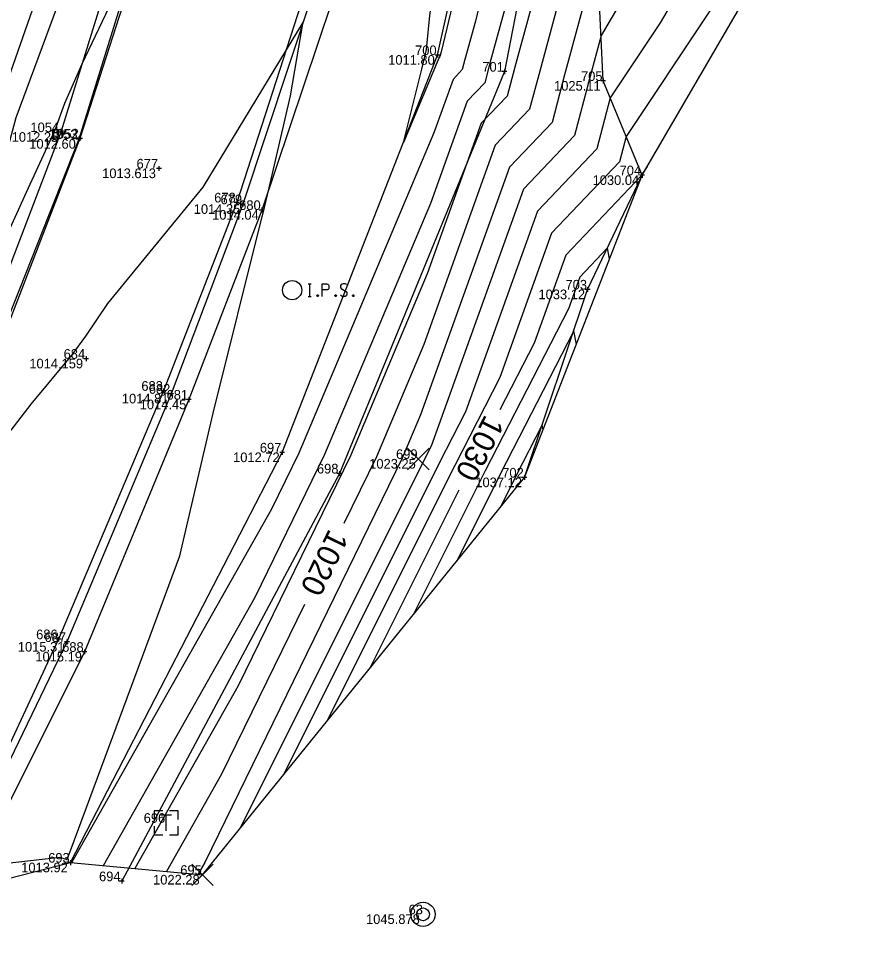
# Model space of a CAD drawing. Extents: x 2354693 to 2355622, y 637071 to 710080.
# Drawn here: x 2355324.5 to 2355430.4, y 708993.3 to 709108.7 of the extents above; entities that cross this region are included whole.
import ezdxf

# ---------------------------------------------------------------- set-up
doc = ezdxf.new("R2010")
doc.units = 0
for name, color, linetype in [('Default', 7, 'Continuous'), ('DT_X_Contour_Major', 7, 'Continuous'), ('DT_X_Contour_Minor', 7, 'Continuous'), ('PM_X_Surveyed_Line', 7, 'Continuous'), ('PV_X_EOP', 7, 'Continuous'), ('PV_X_Shoulder', 7, 'Continuous'), ('SV_P_Mon_Cells_Set', 7, 'Continuous'), ('SV_X_Mon_Cells_Found', 7, 'Continuous'), ('SV_X_Random_Point', 7, 'Continuous'), ('SV_X_Shot_Marker', 7, 'Continuous'), ('SV_X_Text_Elevation', 7, 'Continuous'), ('SV_X_Text_Name', 7, 'Continuous'), ('SV_X_Toe_of_Slope', 7, 'Continuous'), ('SV_X_Top_of_Bank', 7, 'Continuous'), ('UT_X_Telecom_Cells', 7, 'Continuous'), ('VG_X_Tree_Line_Rt', 7, 'Continuous')]:
    doc.layers.add(name, color=color, linetype=linetype)

msp = doc.modelspace()

# ---------------------------------------------------------------- linework, layer by layer
at = {"layer": 'Default'}
msp.add_lwpolyline([(2355263.76, 708986.4), (2355330.91, 709003.61), (2355347.35, 709002.09), (2355387.45, 709051.54), (2355402.1, 709089.16), (2355425.96, 709130.16), (2355495.56, 709194.41), (2355530.33, 709221.46), (2355525, 709302.12), (2355509.66, 709318.33), (2355534.8, 709413.26), (2355566.11, 709428.47), (2355585.74, 709473.78), (2355589.64, 709532.44), (2355608.23, 709591.27)], dxfattribs=at)
msp.add_lwpolyline([(2355263.76, 708986.4), (2355330.91, 709003.61), (2355347.35, 709002.09), (2355387.45, 709051.54), (2355402.1, 709089.16), (2355425.96, 709130.16), (2355495.56, 709194.41), (2355530.33, 709221.46), (2355525, 709302.12), (2355509.66, 709318.33), (2355534.8, 709413.26), (2355566.11, 709428.47), (2355585.74, 709473.78), (2355589.64, 709532.44), (2355608.23, 709591.27)], dxfattribs=at)
at = {"layer": 'DT_X_Contour_Major'}
for points in [[(2355347.04, 709193.49), (2355347.17, 709190.66), (2355346.28, 709182.54), (2355344.27, 709168.58), (2355339.69, 709145.3), (2355339.23, 709144.66), (2355328.8, 709128.82), (2355329.27, 709120.28), (2355328.85, 709117.46), (2355322.25, 709098.57)], [(2355347.04, 709193.49), (2355347.17, 709190.66), (2355346.28, 709182.54), (2355344.27, 709168.58), (2355339.69, 709145.3), (2355339.23, 709144.66), (2355328.8, 709128.82), (2355329.27, 709120.28), (2355328.85, 709117.46), (2355322.25, 709098.57)], [(2355399.81, 709138.75), (2355397.63, 709133.42), (2355395.27, 709124.59), (2355394.15, 709119.88), (2355389.34, 709102.14), (2355388.09, 709097.39), (2355383.82, 709092.9), (2355374.92, 709068.12), (2355369.01, 709054.1), (2355364.95, 709045.81)], [(2355399.81, 709138.75), (2355397.63, 709133.42), (2355395.27, 709124.59), (2355394.15, 709119.88), (2355389.34, 709102.14), (2355388.09, 709097.39), (2355383.82, 709092.9), (2355374.92, 709068.12), (2355369.01, 709054.1), (2355364.95, 709045.81)], [(2355402.74, 709090.26), (2355402.07, 709089.24), (2355402.06, 709089.19), (2355392.58, 709079.22), (2355388.65, 709068.27), (2355384.38, 709059.96)], [(2355402.74, 709090.26), (2355402.07, 709089.24), (2355402.06, 709089.19), (2355392.58, 709079.22), (2355388.65, 709068.27), (2355384.38, 709059.96)], [(2355379.29, 709049.98), (2355368.2, 709027.8)], [(2355379.29, 709049.98), (2355368.2, 709027.8)], [(2355360.04, 709035.75), (2355349.73, 709014.64), (2355342.86, 709002.51)], [(2355360.04, 709035.75), (2355349.73, 709014.64), (2355342.86, 709002.51)]]:
    msp.add_lwpolyline(points, dxfattribs=at)
at = {"layer": 'DT_X_Contour_Minor'}
for points in [[(2355432.86, 709227.06), (2355429.2, 709222.75), (2355423.82, 709215.5), (2355413.6, 709196.23), (2355417.38, 709191.51), (2355406.15, 709181.07), (2355401.67, 709175.4), (2355399.28, 709169.52), (2355396.31, 709163.17), (2355393.28, 709154.48), (2355391.12, 709148.5), (2355389.3, 709141.69), (2355381.34, 709108.35), (2355380.04, 709103.59), (2355379.71, 709102.31), (2355378.56, 709101.1), (2355376.17, 709094.45), (2355359.35, 709054.56), (2355355.96, 709047.61), (2355331.07, 709003.59)], [(2355432.86, 709227.06), (2355429.2, 709222.75), (2355423.82, 709215.5), (2355413.6, 709196.23), (2355417.38, 709191.51), (2355406.15, 709181.07), (2355401.67, 709175.4), (2355399.28, 709169.52), (2355396.31, 709163.17), (2355393.28, 709154.48), (2355391.12, 709148.5), (2355389.3, 709141.69), (2355381.34, 709108.35), (2355380.04, 709103.59), (2355379.71, 709102.31), (2355378.56, 709101.1), (2355376.17, 709094.45), (2355359.35, 709054.56), (2355355.96, 709047.61), (2355331.07, 709003.59)], [(2355433.91, 709212.05), (2355427.03, 709199.09), (2355429.57, 709195.91), (2355410.59, 709178.28), (2355405.76, 709172.16), (2355404.34, 709170.04), (2355400.84, 709164.36), (2355398.86, 709160.13), (2355398.29, 709158.51), (2355394.5, 709147.97), (2355391.29, 709135.99), (2355385.61, 709112.19), (2355383.14, 709103.1), (2355382.5, 709100.67), (2355380.31, 709098.37), (2355375.75, 709085.67), (2355362.57, 709054.41), (2355353.88, 709036.62), (2355335, 709003.23)], [(2355433.91, 709212.05), (2355427.03, 709199.09), (2355429.57, 709195.91), (2355410.59, 709178.28), (2355405.76, 709172.16), (2355404.34, 709170.04), (2355400.84, 709164.36), (2355398.86, 709160.13), (2355398.29, 709158.51), (2355394.5, 709147.97), (2355391.29, 709135.99), (2355385.61, 709112.19), (2355383.14, 709103.1), (2355382.5, 709100.67), (2355380.31, 709098.37), (2355375.75, 709085.67), (2355362.57, 709054.41), (2355353.88, 709036.62), (2355335, 709003.23)], [(2355455.82, 709201.52), (2355428.34, 709177.87), (2355423.54, 709166.09), (2355421.9, 709163.64), (2355420.2, 709160.88), (2355416.62, 709155.81), (2355407.85, 709141.74), (2355400.15, 709122.88), (2355396.5, 709116.66), (2355392.43, 709101.65), (2355390.88, 709095.75), (2355385.57, 709090.16), (2355374.5, 709059.34), (2355372.23, 709053.95), (2355347.65, 709003.65), (2355346.79, 709002.14)], [(2355455.82, 709201.52), (2355428.34, 709177.87), (2355423.54, 709166.09), (2355421.9, 709163.64), (2355420.2, 709160.88), (2355416.62, 709155.81), (2355407.85, 709141.74), (2355400.15, 709122.88), (2355396.5, 709116.66), (2355392.43, 709101.65), (2355390.88, 709095.75), (2355385.57, 709090.16), (2355374.5, 709059.34), (2355372.23, 709053.95), (2355347.65, 709003.65), (2355346.79, 709002.14)], [(2355401.7, 709183.87), (2355400.31, 709182.11), (2355394.55, 709167.89), (2355393.76, 709166.21), (2355388.26, 709150.46), (2355387.74, 709149.02), (2355387.31, 709147.39), (2355377.07, 709104.51), (2355376.95, 709104.07), (2355376.92, 709103.95), (2355376.81, 709103.84), (2355376.59, 709103.23), (2355372.38, 709093.25), (2355374.65, 709102.38), (2355375.23, 709104.82), (2355375.66, 709109.07), (2355380.92, 709145.65), (2355381.7, 709154.71), (2355384.94, 709165.98), (2355388.38, 709181.55), (2355387.25, 709201.61)], [(2355401.7, 709183.87), (2355400.31, 709182.11), (2355394.55, 709167.89), (2355393.76, 709166.21), (2355388.26, 709150.46), (2355387.74, 709149.02), (2355387.31, 709147.39), (2355377.07, 709104.51), (2355376.95, 709104.07), (2355376.92, 709103.95), (2355376.81, 709103.84), (2355376.59, 709103.23), (2355372.38, 709093.25), (2355374.65, 709102.38), (2355375.23, 709104.82), (2355375.66, 709109.07), (2355380.92, 709145.65), (2355381.7, 709154.71), (2355384.94, 709165.98), (2355388.38, 709181.55), (2355387.25, 709201.61)], [(2355441.77, 709200.32), (2355421.1, 709181.12), (2355415.48, 709176.27), (2355415, 709175.1), (2355410.19, 709167.9), (2355405.21, 709159.83), (2355399.33, 709151.49), (2355397.87, 709147.45), (2355393.28, 709130.29), (2355389.88, 709116.04), (2355386.24, 709102.62), (2355385.3, 709099.03), (2355382.07, 709095.63), (2355375.33, 709076.89), (2355365.79, 709054.26), (2355351.8, 709025.63), (2355338.93, 709002.87)], [(2355441.77, 709200.32), (2355421.1, 709181.12), (2355415.48, 709176.27), (2355415, 709175.1), (2355410.19, 709167.9), (2355405.21, 709159.83), (2355399.33, 709151.49), (2355397.87, 709147.45), (2355393.28, 709130.29), (2355389.88, 709116.04), (2355386.24, 709102.62), (2355385.3, 709099.03), (2355382.07, 709095.63), (2355375.33, 709076.89), (2355365.79, 709054.26), (2355351.8, 709025.63), (2355338.93, 709002.87)], [(2355362.05, 709192.16), (2355358.45, 709172.04), (2355357.11, 709166.59), (2355354.46, 709157.07), (2355350.37, 709143.12), (2355339.59, 709118.3), (2355339.54, 709118.17), (2355339.49, 709118.02), (2355332.34, 709102.98), (2355330.16, 709098.09), (2355328.96, 709094.77), (2355325.41, 709087), (2355319.12, 709073.27), (2355312.74, 709068.84), (2355306.43, 709059.31), (2355290.09, 709038.24), (2355286.78, 709031.66), (2355285.96, 709030.24), (2355285.39, 709028.91), (2355262.53, 708987.18)], [(2355362.05, 709192.16), (2355358.45, 709172.04), (2355357.11, 709166.59), (2355354.46, 709157.07), (2355350.37, 709143.12), (2355339.59, 709118.3), (2355339.54, 709118.17), (2355339.49, 709118.02), (2355332.34, 709102.98), (2355330.16, 709098.09), (2355328.96, 709094.77), (2355325.41, 709087), (2355319.12, 709073.27), (2355312.74, 709068.84), (2355306.43, 709059.31), (2355290.09, 709038.24), (2355286.78, 709031.66), (2355285.96, 709030.24), (2355285.39, 709028.91), (2355262.53, 708987.18)], [(2355434.77, 709178.67), (2355427.81, 709161.59), (2355427.75, 709161.5), (2355427.69, 709161.4), (2355427.56, 709161.22), (2355413.25, 709138.29), (2355407.86, 709125.05), (2355396.98, 709106.54), (2355395.53, 709101.17), (2355393.68, 709094.11), (2355387.32, 709087.42), (2355375.84, 709055.46), (2355374.95, 709053.73), (2355351.99, 709007.81)], [(2355434.77, 709178.67), (2355427.81, 709161.59), (2355427.75, 709161.5), (2355427.69, 709161.4), (2355427.56, 709161.22), (2355413.25, 709138.29), (2355407.86, 709125.05), (2355396.98, 709106.54), (2355395.53, 709101.17), (2355393.68, 709094.11), (2355387.32, 709087.42), (2355375.84, 709055.46), (2355374.95, 709053.73), (2355351.99, 709007.81)], [(2355443.81, 709170.88), (2355426.26, 709134.89), (2355424.07, 709131.37), (2355423.26, 709129.4), (2355420.36, 709124.46), (2355400.1, 709094.01), (2355399.26, 709090.83), (2355390.83, 709081.95), (2355384.38, 709064), (2355378.76, 709053.06), (2355362.8, 709021.14)], [(2355443.81, 709170.88), (2355426.26, 709134.89), (2355424.07, 709131.37), (2355423.26, 709129.4), (2355420.36, 709124.46), (2355400.1, 709094.01), (2355399.26, 709090.83), (2355390.83, 709081.95), (2355384.38, 709064), (2355378.76, 709053.06), (2355362.8, 709021.14)], [(2355435.74, 709166.06), (2355427.13, 709148.41), (2355418.66, 709134.83), (2355415.56, 709127.23), (2355404.35, 709108.14), (2355398.13, 709098.79), (2355396.47, 709092.47), (2355389.07, 709084.69), (2355380.11, 709059.73), (2355376.86, 709053.4), (2355357.39, 709014.47)], [(2355435.74, 709166.06), (2355427.13, 709148.41), (2355418.66, 709134.83), (2355415.56, 709127.23), (2355404.35, 709108.14), (2355398.13, 709098.79), (2355396.47, 709092.47), (2355389.07, 709084.69), (2355380.11, 709059.73), (2355376.86, 709053.4), (2355357.39, 709014.47)], [(2355355.09, 709085.15), (2355355.66, 709087.58), (2355358.32, 709099.04), (2355359.91, 709108.28), (2355347.41, 709087.68), (2355335.52, 709073.22), (2355332.79, 709069.12), (2355331.08, 709066.83), (2355325.98, 709060.69), (2355315.72, 709047.38)], [(2355355.09, 709085.15), (2355355.66, 709087.58), (2355358.32, 709099.04), (2355359.91, 709108.28), (2355347.41, 709087.68), (2355335.52, 709073.22), (2355332.79, 709069.12), (2355331.08, 709066.83), (2355325.98, 709060.69), (2355315.72, 709047.38)], [(2355283.94, 708999.11), (2355329.58, 709004.31), (2355330.45, 709003.99), (2355330.51, 709004.01), (2355331.02, 709005.34), (2355344.54, 709041.8), (2355348.67, 709059.54), (2355354.8, 709084.02), (2355355.09, 709085.15)], [(2355283.94, 708999.11), (2355329.58, 709004.31), (2355330.45, 709003.99), (2355330.51, 709004.01), (2355331.02, 709005.34), (2355344.54, 709041.8), (2355348.67, 709059.54), (2355354.8, 709084.02), (2355355.09, 709085.15)], [(2355398.04, 709078.73), (2355397.79, 709080.12), (2355394.33, 709076.48), (2355392.91, 709072.54), (2355382.57, 709052.39), (2355373.6, 709034.46)], [(2355398.04, 709078.73), (2355397.79, 709080.12), (2355394.33, 709076.48), (2355392.91, 709072.54), (2355382.57, 709052.39), (2355373.6, 709034.46)], [(2355393.91, 709068.12), (2355393.59, 709069.82), (2355384.47, 709052.06), (2355379.01, 709041.13)], [(2355393.91, 709068.12), (2355393.59, 709069.82), (2355384.47, 709052.06), (2355379.01, 709041.13)], [(2355389.77, 709057.5), (2355389.66, 709058.11), (2355386.38, 709051.72), (2355384.41, 709047.79)], [(2355389.77, 709057.5), (2355389.66, 709058.11), (2355386.38, 709051.72), (2355384.41, 709047.79)]]:
    msp.add_lwpolyline(points, dxfattribs=at)
at = {"layer": 'PM_X_Surveyed_Line'}
for points in [[(2355180.15, 709561.24), (2355214.75, 709522.89), (2355249.31, 709484.27), (2355284.02, 709443.14), (2355315.55, 709399.77), (2355328.89, 709377.57), (2355342.97, 709349.79), (2355353.37, 709324.19), (2355361.35, 709299.65), (2355367.76, 709272.47), (2355372.19, 709243.49), (2355373.87, 709217.88), (2355371.21, 709164.41), (2355367.13, 709139.62), (2355360.06, 709111.88), (2355351.62, 709085.78), (2355342.5, 709062.34), (2355329.45, 709031.42), (2355320.62, 709012.58)], [(2355165.86, 709547.27), (2355199.55, 709510.04), (2355233.99, 709470.59), (2355267.54, 709430.37), (2355282.6, 709410.56), (2355297.68, 709388.57), (2355309.4, 709369.45), (2355323.83, 709342.43), (2355334.06, 709318.38), (2355342.29, 709293.43), (2355348.47, 709267.17), (2355351.87, 709240.38), (2355352.96, 709217.38), (2355352.46, 709191.09), (2355350.19, 709167.62), (2355345.96, 709144.01), (2355339.85, 709117.86), (2355332.1, 709093.74), (2355322.6, 709069.08), (2355314.61, 709050.66), (2355300.36, 709021.7)]]:
    msp.add_lwpolyline(points, dxfattribs=at)
at = {"layer": 'PV_X_EOP'}
for points in [[(2355180.81, 709561.74), (2355215.64, 709523.56), (2355249.92, 709484.36), (2355284.41, 709443.36), (2355315.94, 709399.97), (2355329.75, 709378.36), (2355343.52, 709350.1), (2355349.22, 709351.4), (2355359.3, 709326.8), (2355367.59, 709301.75), (2355374.11, 709275.91), (2355368.17, 709272.69), (2355372.5, 709243.56), (2355374.5, 709217.66), (2355371.41, 709164.43), (2355367.84, 709139.33), (2355361.02, 709111.64), (2355352.39, 709085.56), (2355343.44, 709061.97), (2355330.49, 709031.08), (2355321.14, 709011.8)], [(2355165.32, 709546.95), (2355198.99, 709509.5), (2355233.4, 709470.11), (2355266.73, 709429.76), (2355281.93, 709410.08), (2355297.05, 709388.17), (2355308.64, 709369.04), (2355321.45, 709342.93), (2355321.34, 709342.62), (2355331.82, 709317.68), (2355340.04, 709292.97), (2355346.6, 709266.72), (2355349.96, 709239.9), (2355351.76, 709217.38), (2355351.56, 709190.76), (2355349.32, 709167.66), (2355345.61, 709144.12), (2355339.52, 709118.01), (2355331.95, 709093.67), (2355322.31, 709069.24), (2355314.27, 709051.11), (2355300.29, 709022.25)]]:
    msp.add_lwpolyline(points, dxfattribs=at)
at = {"layer": 'PV_X_Shoulder'}
for points in [[(2355370.56, 709271.65), (2355375.13, 709244.15), (2355376.46, 709217.44), (2355373.31, 709164.03), (2355369.83, 709138.83), (2355363.46, 709110.73), (2355354.73, 709084.84), (2355345.67, 709061.24), (2355332.68, 709029.85), (2355323.4, 709011.31)], [(2355350.69, 709226.18), (2355349.24, 709225.72), (2355348.98, 709190.63), (2355347.11, 709167.94), (2355343.48, 709144.04), (2355337.29, 709118.88), (2355329.72, 709094.53), (2355320.78, 709071.24), (2355312.54, 709052.23), (2355299, 709024.07)]]:
    msp.add_lwpolyline(points, dxfattribs=at)
at = {"layer": 'SV_P_Mon_Cells_Set'}
for points in [[(2355360.53, 709075.67), (2355360.89, 709075.67)], [(2355360.71, 709074.07), (2355360.71, 709075.67)], [(2355362.28, 709074.07), (2355362.28, 709075.67), (2355362.81, 709075.67), (2355362.86, 709075.66), (2355362.94, 709075.63), (2355362.97, 709075.61), (2355363, 709075.58), (2355363.05, 709075.52), (2355363.08, 709075.45), (2355363.1, 709075.35), (2355363.1, 709075.2), (2355363.09, 709075.15), (2355363.07, 709075.08), (2355363.03, 709074.99), (2355362.98, 709074.95), (2355362.95, 709074.92), (2355362.89, 709074.9), (2355362.81, 709074.89), (2355362.28, 709074.89)], [(2355365.29, 709075.55), (2355365.26, 709075.58), (2355365.23, 709075.61), (2355365.13, 709075.64), (2355365.01, 709075.67), (2355364.92, 709075.67), (2355364.89, 709075.67), (2355364.75, 709075.63), (2355364.62, 709075.55), (2355364.55, 709075.45), (2355364.53, 709075.35), (2355364.53, 709075.28), (2355364.55, 709075.18), (2355364.64, 709075.09), (2355365.24, 709074.71), (2355365.3, 709074.66), (2355365.32, 709074.61), (2355365.34, 709074.53), (2355365.34, 709074.46), (2355365.33, 709074.38), (2355365.32, 709074.33), (2355365.3, 709074.27), (2355365.27, 709074.22), (2355365.25, 709074.18), (2355365.22, 709074.14), (2355365.19, 709074.12), (2355365.14, 709074.09), (2355365.11, 709074.08), (2355365.01, 709074.07), (2355364.86, 709074.07), (2355364.76, 709074.09), (2355364.61, 709074.18), (2355364.53, 709074.26)], [(2355360.53, 709074.07), (2355360.89, 709074.07)], [(2355361.67, 709074.28), (2355361.73, 709074.28), (2355361.76, 709074.26), (2355361.79, 709074.21), (2355361.79, 709074.14), (2355361.76, 709074.09), (2355361.73, 709074.07), (2355361.67, 709074.07), (2355361.64, 709074.09), (2355361.6, 709074.14), (2355361.6, 709074.21), (2355361.64, 709074.26), (2355361.67, 709074.28)], [(2355363.92, 709074.28), (2355363.97, 709074.28), (2355364.01, 709074.26), (2355364.04, 709074.21), (2355364.04, 709074.14), (2355364.01, 709074.09), (2355363.97, 709074.07), (2355363.92, 709074.07), (2355363.89, 709074.09), (2355363.85, 709074.14), (2355363.85, 709074.21), (2355363.89, 709074.26), (2355363.92, 709074.28)], [(2355366.1, 709074.28), (2355366.16, 709074.28), (2355366.19, 709074.26), (2355366.22, 709074.21), (2355366.22, 709074.14), (2355366.19, 709074.09), (2355366.16, 709074.07), (2355366.1, 709074.07), (2355366.07, 709074.09), (2355366.04, 709074.14), (2355366.04, 709074.21), (2355366.07, 709074.26), (2355366.1, 709074.28)]]:
    msp.add_lwpolyline(points, dxfattribs=at)
msp.add_circle((2355358.52, 709074.87), 1.2, dxfattribs=at)
at = {"layer": 'SV_X_Mon_Cells_Found'}
for radius in [1.5, 0.8]:
    msp.add_circle((2355374.82, 708997.18), radius, dxfattribs=at)
at = {"layer": 'SV_X_Random_Point'}
for p, q in [((2355372.9, 709052.52), (2355375.57, 709055.19)), ((2355372.9, 709055.19), (2355375.57, 709052.52)), ((2355346.02, 709000.76), (2355348.69, 709003.43)), ((2355346.02, 709003.43), (2355348.69, 709000.76))]:
    msp.add_line(p, q, dxfattribs=at)
at = {"layer": 'SV_X_Shot_Marker'}
for p, q in [((2355376.93, 709104.12), (2355376.33, 709104.12)), ((2355376.63, 709104.42), (2355376.63, 709103.82)), ((2355385.27, 709102.06), (2355384.67, 709102.06)), ((2355384.97, 709102.36), (2355384.97, 709101.76)), ((2355397.55, 709100.9), (2355396.95, 709100.9)), ((2355397.25, 709101.2), (2355397.25, 709100.6)), ((2355329.72, 709094.83), (2355329.72, 709094.23)), ((2355330.02, 709094.53), (2355329.42, 709094.53)), ((2355332.25, 709093.67), (2355331.65, 709093.67)), ((2355332.4, 709093.74), (2355331.8, 709093.74)), ((2355331.95, 709093.97), (2355331.95, 709093.37)), ((2355332.1, 709094.04), (2355332.1, 709093.44)), ((2355342.24, 709090.01), (2355341.64, 709090.01)), ((2355341.94, 709090.31), (2355341.94, 709089.71)), ((2355402.4, 709089.16), (2355401.81, 709089.16)), ((2355402.1, 709089.46), (2355402.1, 709088.86)), ((2355351.92, 709085.78), (2355351.32, 709085.78)), ((2355351.62, 709086.08), (2355351.62, 709085.48)), ((2355352.69, 709085.56), (2355352.09, 709085.56)), ((2355352.39, 709085.86), (2355352.39, 709085.26)), ((2355355.03, 709084.84), (2355354.43, 709084.84)), ((2355354.73, 709085.14), (2355354.73, 709084.54)), ((2355395.31, 709075.24), (2355395.31, 709074.64)), ((2355395.61, 709074.94), (2355395.01, 709074.94)), ((2355333.18, 709066.33), (2355332.58, 709066.33)), ((2355332.88, 709066.63), (2355332.88, 709066.03)), ((2355342.8, 709062.34), (2355342.2, 709062.34)), ((2355342.5, 709062.64), (2355342.5, 709062.04)), ((2355343.74, 709061.97), (2355343.14, 709061.97)), ((2355343.44, 709062.27), (2355343.44, 709061.67)), ((2355345.97, 709061.24), (2355345.37, 709061.24)), ((2355345.67, 709061.54), (2355345.67, 709060.94)), ((2355357.59, 709054.66), (2355356.99, 709054.66)), ((2355357.29, 709054.96), (2355357.29, 709054.36)), ((2355364.7, 709052.05), (2355364.1, 709052.05)), ((2355364.4, 709052.35), (2355364.4, 709051.75)), ((2355387.75, 709051.54), (2355387.15, 709051.54)), ((2355387.45, 709051.84), (2355387.45, 709051.24)), ((2355329.75, 709031.42), (2355329.15, 709031.42)), ((2355329.45, 709031.72), (2355329.45, 709031.12)), ((2355330.49, 709031.38), (2355330.49, 709030.78)), ((2355330.79, 709031.08), (2355330.19, 709031.08)), ((2355332.68, 709030.15), (2355332.68, 709029.55)), ((2355332.98, 709029.85), (2355332.38, 709029.85)), ((2355331.21, 709003.61), (2355330.61, 709003.61)), ((2355330.91, 709003.91), (2355330.91, 709003.31)), ((2355337.6, 709001.3), (2355337, 709001.3)), ((2355337.3, 709001.6), (2355337.3, 709001))]:
    msp.add_line(p, q, dxfattribs=at)
at = {"layer": 'SV_X_Toe_of_Slope'}
for points in [[(2355330.91, 709003.61), (2355357.29, 709054.66), (2355376.63, 709104.12), (2355386.68, 709149.19), (2355392.84, 709167.31), (2355399.71, 709185.13), (2355454.61, 709204.96), (2355491.09, 709216.85), (2355522.63, 709235.09)], [(2355341.81, 709169.14), (2355339.63, 709144.67), (2355332.89, 709119.96), (2355324.12, 709096.3), (2355318.2, 709074.39)]]:
    msp.add_lwpolyline(points, dxfattribs=at)
at = {"layer": 'SV_X_Top_of_Bank'}
msp.add_lwpolyline([(2355387.45, 709051.54), (2355395.31, 709074.94), (2355402.1, 709089.16), (2355397.25, 709100.9), (2355396.26, 709121.78), (2355399.27, 709147.23), (2355399.44, 709159.43), (2355402.62, 709170.67), (2355414.05, 709176.1)], dxfattribs=at)
at = {"layer": 'UT_X_Telecom_Cells'}
for p, q in [((2355342.19, 709009.57), (2355343.49, 709009.57)), ((2355342.84, 709007.57), (2355342.84, 709009.57)), ((2355342.84, 709008.57), (2355342.84, 709008.57))]:
    msp.add_line(p, q, dxfattribs=at)
for points in [[(2355342.44, 709010.07), (2355341.34, 709010.07), (2355341.34, 709008.97)], [(2355344.34, 709008.97), (2355344.34, 709010.07), (2355343.24, 709010.07)], [(2355341.34, 709008.17), (2355341.34, 709007.07), (2355342.44, 709007.07)], [(2355343.24, 709007.07), (2355344.34, 709007.07), (2355344.34, 709008.17)]]:
    msp.add_lwpolyline(points, dxfattribs=at)
at = {"layer": 'VG_X_Tree_Line_Rt'}
msp.add_lwpolyline([(2355430.11, 709344.44), (2355398.4, 709251.33), (2355397.95, 709252.38), (2355395.76, 709165.3), (2355393.83, 709147.98), (2355384.97, 709102.06), (2355364.4, 709052.05), (2355337.3, 709001.3)], dxfattribs=at)

# ---------------------------------------------------------------- texts
at = {"layer": 'DT_X_Contour_Major'}
for s, rotation, p in [('1030', 242.99, (2355382.55, 709059.49)), ('1030', 242.99, (2355382.55, 709059.49)), ('1020', 243.9576, (2355363.13, 709045.26)), ('1020', 243.9576, (2355363.13, 709045.26))]:
    msp.add_text(s, height=2.8, rotation=rotation, dxfattribs=at).set_placement(p)
at = {"layer": 'SV_X_Text_Elevation'}
for s, p in [('1011.80', (2355370.48, 709102.92)), ('1025.11', (2355391.13, 709099.7)), ('1012.25', (2355323.6, 709093.33)), ('1012.60', (2355325.79, 709092.47)), ('1013.613', (2355334.87, 709088.81)), ('1030.04', (2355395.93, 709087.96)), ('1014.35', (2355346.27, 709084.36)), ('1014.04', (2355348.56, 709083.64)), ('1033.12', (2355389.19, 709073.74)), ('1014.159', (2355325.8, 709065.13)), ('1014.81', (2355337.32, 709060.77)), ('1014.45', (2355339.55, 709060.04)), ('1012.72', (2355351.17, 709053.46)), ('1023.25', (2355368.12, 709052.66)), ('1037.12', (2355381.33, 709050.34)), ('1015.31', (2355324.37, 709029.88)), ('1015.19', (2355326.55, 709028.65)), ('1013.92', (2355324.79, 709002.41)), ('1022.28', (2355341.21, 709000.89)), ('1045.878', (2355367.72, 708995.98))]:
    msp.add_text(s, height=1.2, dxfattribs=at).set_placement(p)
at = {"layer": 'SV_X_Text_Name'}
for s, p in [('700', (2355373.83, 709104.12)), ('701', (2355382.2, 709102.06)), ('705', (2355394.49, 709100.9)), ('1054', (2355325.94, 709094.53)), ('1053', (2355328.23, 709093.67)), ('1052', (2355328.38, 709093.74)), ('677', (2355339.15, 709090.01)), ('704', (2355399.29, 709089.16)), ('678', (2355348.82, 709085.78)), ('679', (2355349.61, 709085.56)), ('680', (2355351.93, 709084.84)), ('703', (2355392.56, 709074.94)), ('684', (2355330.07, 709066.33)), ('683', (2355339.75, 709062.34)), ('682', (2355340.68, 709061.97)), ('681', (2355342.89, 709061.24)), ('697', (2355354.5, 709054.66)), ('699', (2355371.46, 709053.86)), ('698', (2355361.61, 709052.05)), ('702', (2355384.68, 709051.54)), ('686', (2355326.65, 709031.42)), ('687', (2355327.7, 709031.08)), ('688', (2355329.89, 709029.85)), ('696', (2355340.04, 709008.57)), ('693', (2355328.15, 709003.61)), ('694', (2355334.48, 709001.3)), ('695', (2355344.59, 709002.09)), ('63', (2355373.02, 708997.18))]:
    msp.add_text(s, height=1.2, dxfattribs=at).set_placement(p)

doc.saveas('drawing.dxf')
